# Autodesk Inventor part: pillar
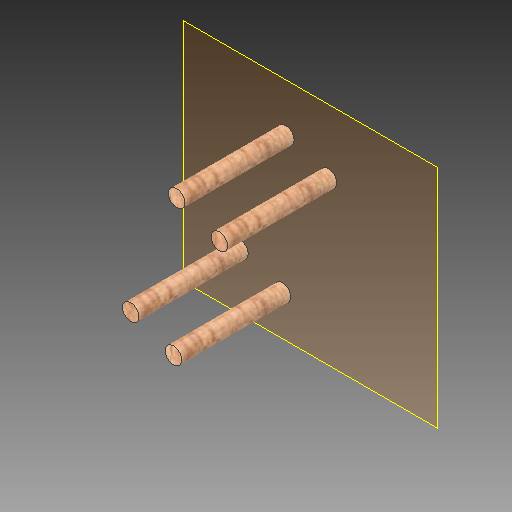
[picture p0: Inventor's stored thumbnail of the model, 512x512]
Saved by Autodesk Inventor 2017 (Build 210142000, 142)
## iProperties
Created: 2017-05
Part Number: pillar
Material: Wood (Birch)
Document SubType Name: Modeling
Designer: 1717440
Density: 0.55 g/cm^3
Appearance: Birch - Natural Polished
Author: 1717440
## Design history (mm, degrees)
workplane "Work Plane1"
sketch "Sketch1"
  geometry: C1 r 6.425 at (32.658, 14.741) reference; C2 r 6.425 at (-0.085, 27.105) reference; C3 r 6.425 at (-35.412, -66.447) reference; C4 r 6.425 at (-2.668, -78.811) reference; C5 r 6.35 at (-0.085, 27.105); C6 r 6.35 at (32.658, 14.741); C7 r 6.35 at (-35.412, -66.447); C8 r 6.35 at (-2.668, -78.811); 1 further point
  constraints: 4 centre point, 4 coincident
  dimensions: "d0" = 12.7 diameter of C5; "d1" = 12.7 diameter of C6; "d2" = 12.7 diameter of C7; "d3" = 12.7 diameter of C8
  node "Reference1"
  node "Reference2"
  node "Reference3"
  node "Reference4"
workplane "Work Plane2"
extrude "Extrusion1" new body sketch "Sketch1" stored distance "d4" = 10; taper "d5" = 0 deg
body "Solid1"
